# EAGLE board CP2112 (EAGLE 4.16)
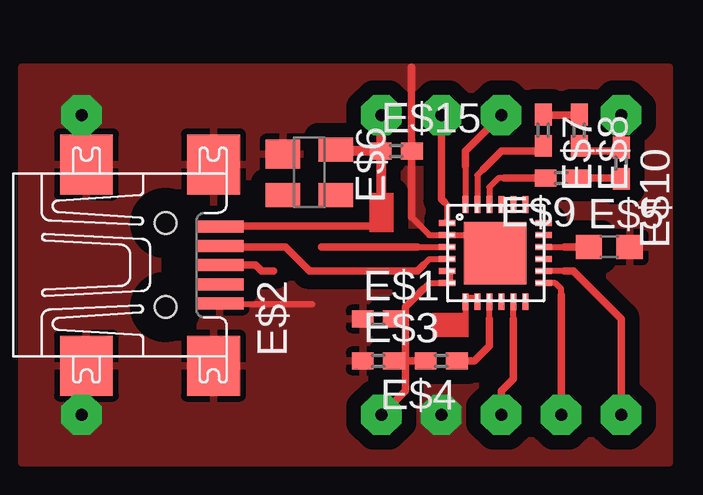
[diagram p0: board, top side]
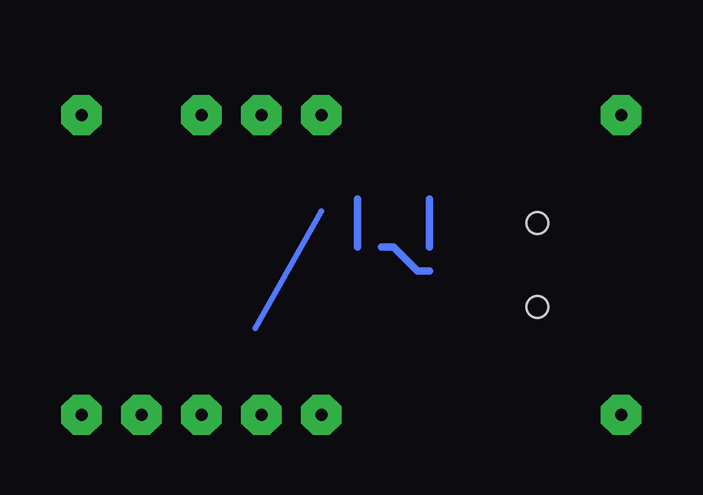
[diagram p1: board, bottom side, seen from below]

No outline drawn. Coordinates in mm, seen from the top.
Copper layers (1*16): Top 0.035mm / dielectric 1.5mm / Bottom 0.035mm
Design rules "default": minimum track width 10mil, minimum drill 24mil, track to track 8mil, track to pad 8mil, pad to pad 8mil, via to via 8mil, smd to smd 8mil, copper to edge 40mil, drill to drill 8mil, minimum pad ring 10mil, minimum via ring 8mil, stop-mask expansion 4mil, vias tented up to drill 0mil, thermal gap 10mil

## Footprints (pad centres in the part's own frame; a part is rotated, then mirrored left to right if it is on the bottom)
C0402 = smd 0.9 x 0.7: 1 -0.65,0; 2 0.65,0
UX60-MB-5ST = smd 2 x 0.5: 1 2.25,1.6; 2 2.25,0.8; 3 2.25,0; 4 2.25,-0.8; 5 2.25,-1.6 | smd 2.2 x 2.5: M1 -3.3,-4.2; M2 -3.3,4.2; M3 2,4.2; M4 2,-4.2 | hole 0.9: 0,-1.75; 0,1.75
C0603 = smd 1.1 x 1: 1 -0.85,0; 2 0.85,0
SOT143 = smd 1.2 x 1.44: 1 -0.75,-1.1 | smd 1 x 1.44: 2 0.95,-1.1; 3 0.95,1.1; 4 -0.95,1.1
QFN24NEW = smd 0.7 x 0.25: 1 -2.005,1.25; 2 -2.005,0.75; 3 -2.005,0.25; 4 -2.005,-0.25; 5 -2.005,-0.75; 6 -2.005,-1.25; 13 2.02,-1.25; 14 2.02,-0.75; 15 2.02,-0.25; 16 2.02,0.25; 17 2.02,0.75; 18 2.02,1.25 | smd 0.25 x 0.7: 7 -0.75,-2.03; 8 -0.25,-2.03; 9 0.25,-2.03; 10 0.75,-2.03; 11 1.25,-2.03; 12 -1.25,2.02; 25 -1.25,-2.03; 26 -0.75,2.02; 27 -0.25,2.02; 28 0.25,2.02; 29 0.75,2.02; 30 1.25,2.02 | smd 2.6 x 2.6: P$25 -0.005,0

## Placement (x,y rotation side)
E$1  [C0402]  14.88,6 0 top
E$2  [UX60-MB-5ST]  6,8.25 0 top
E$3  [C0402]  14.88,4.25 0 top
E$4  [C0402]  17.5,4.25 180 top
E$5  [C0603]  24.5,9 0 top
E$6  [SOT143]  12,12.12 270 top
E$7  [C0402]  21.75,13.88 270 top
E$8  [C0402]  23.25,13.88 270 top
E$9  [C0402]  22.5,11.88 180 top
E$10  [C0402]  25,12.5 270 top
E$14  [QFN24NEW]  19.75,8.75 0 top
E$15  [C0402]  15.62,13 0 top

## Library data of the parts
E$1 E$3-E$10 E$15 = ref-packages
E$2 = con-hirose
E$14 = TI_MSP430_v122

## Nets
GND: E$1.1 E$2.5 E$2.M1 E$2.M2 E$2.M3 E$2.M4 E$3.1 E$5.2 E$6.1 E$15.2

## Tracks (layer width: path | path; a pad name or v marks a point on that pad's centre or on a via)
D-
  Top 0.254: 17.5,8.5 17,8.5 16.75,8.25
  Top 0.305: 8.12,9 11,9 12,8 16.5,8 16.75,8.25
GND  (via drill 0.5 pad 1.68)
  Top 0.254: 8.25,6.62 12.12,6.62 | 19,9.5 17,9.5 16.25,10.25
  Top 0.305: 16.25,10.25 16.25,12.75 16.38,13 16.38,13.12 16.25,13.25 16.25,16.5
  other vias: 17.5,2 2.5,2 2.5,14.5
  pour Top (isolate 0.61): 0,0 0,16.5 27,16.5 27,0
S$1
  Bottom 0.254: 17.75,5.62 15,10.5
S$2
  Top 0.254: 22,9 22.62,9
  Top 0.305: 22.62,9 23.5,9
S$3
  Top 0.254: 19,6.88 18.5,6.88
S$4
  Bottom 0.305: 10.5,9 10.5,11
S$5
  Bottom 0.305: 13.5,9 13.5,11
S$6
  Top 0.254: 18.5,6.5 18.5,5.88
S$7
  Top 0.254: 18.5,12.38 18.5,11
  Top 0.305: 18.5,12.38 18.5,13 20,14.5
S$8
  Top 0.254: 17.75,10 17.75,10.75 17.62,10.88
  Top 0.305: 17.62,10.88 17.5,11 17.5,14.5
S$9  (via drill 0.5 pad 1.68)
  other vias: 17.5,14.5
S$10
  Top 0.305: 21.75,14.5 23.25,14.5
S$11  (via drill 0.5 pad 1.68)
  other vias: 20,14.5
S$12  (via drill 0.5 pad 1.68)
  Top 0.406: 15,9.88 15,13 | 15,13 v15,14.5 | 15,13 13.5,13
S$13
  Top 0.254: 19.5,6 19.5,6.5
  Top 0.305: 18.5,4.25 18.88,4.25 19.5,4.88 19.5,6
S$14
  Top 0.254: 19,11 19,12 19.25,12.25
  Top 0.305: 19.25,12.25 20,13 21.75,13
S$15  (via drill 0.5 pad 1.68)
  Top 0.254: 20.5,6 20.5,6.5
  Top 0.305: 20.5,6 20.5,3.5 20,3 v20,2
S$16
  Top 0.254: 19.5,11 19.5,11.5 19.88,11.88 20.12,11.88
  Top 0.305: 20.12,11.88 21.88,11.88
S$17
  Top 0.305: 23.25,13 25,13 25,14.5
S$18
  Top 0.305: 24.88,11.88 23.5,11.88
S$19  (via drill 0.5 pad 1.68)
  Top 0.254: 17.88,7.88 17.88,7.5 17,7.5 16.75,7.25
  Top 0.305: 16.75,7.25 16,6.5 16,4.25 | 16,4.25 16,3 v15,2 | 16,4.25 17,4.25
S$20  (via drill 0.5 pad 1.68)
  other vias: 25,14.5
S$21
  Top 0.254: 16.5,9 17.5,9
  Top 0.305: 12.5,9 16.5,9
S$22
  Bottom 0.305: 10.5,8 11,8 12,9 12.5,9
S$23  (via drill 0.5 pad 1.68)
  Top 0.254: 22,7.5 22.25,7.5 22.5,7.25 22.5,7
  Top 0.305: v22.5,2 22.5,7
S$25
  Top 0.305: 9,9.88 15,9.88
S$26  (via drill 0.5 pad 1.68)
  Top 0.254: 22.62,8 22,8
  Top 0.305: 22.62,8 23,8 25,6 v25,2
S$27
  Top 0.305: 8.5,8.25 9.75,8.25 10,8 10.5,8
(copper drawn outside any net)
  shapes: Top area x2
